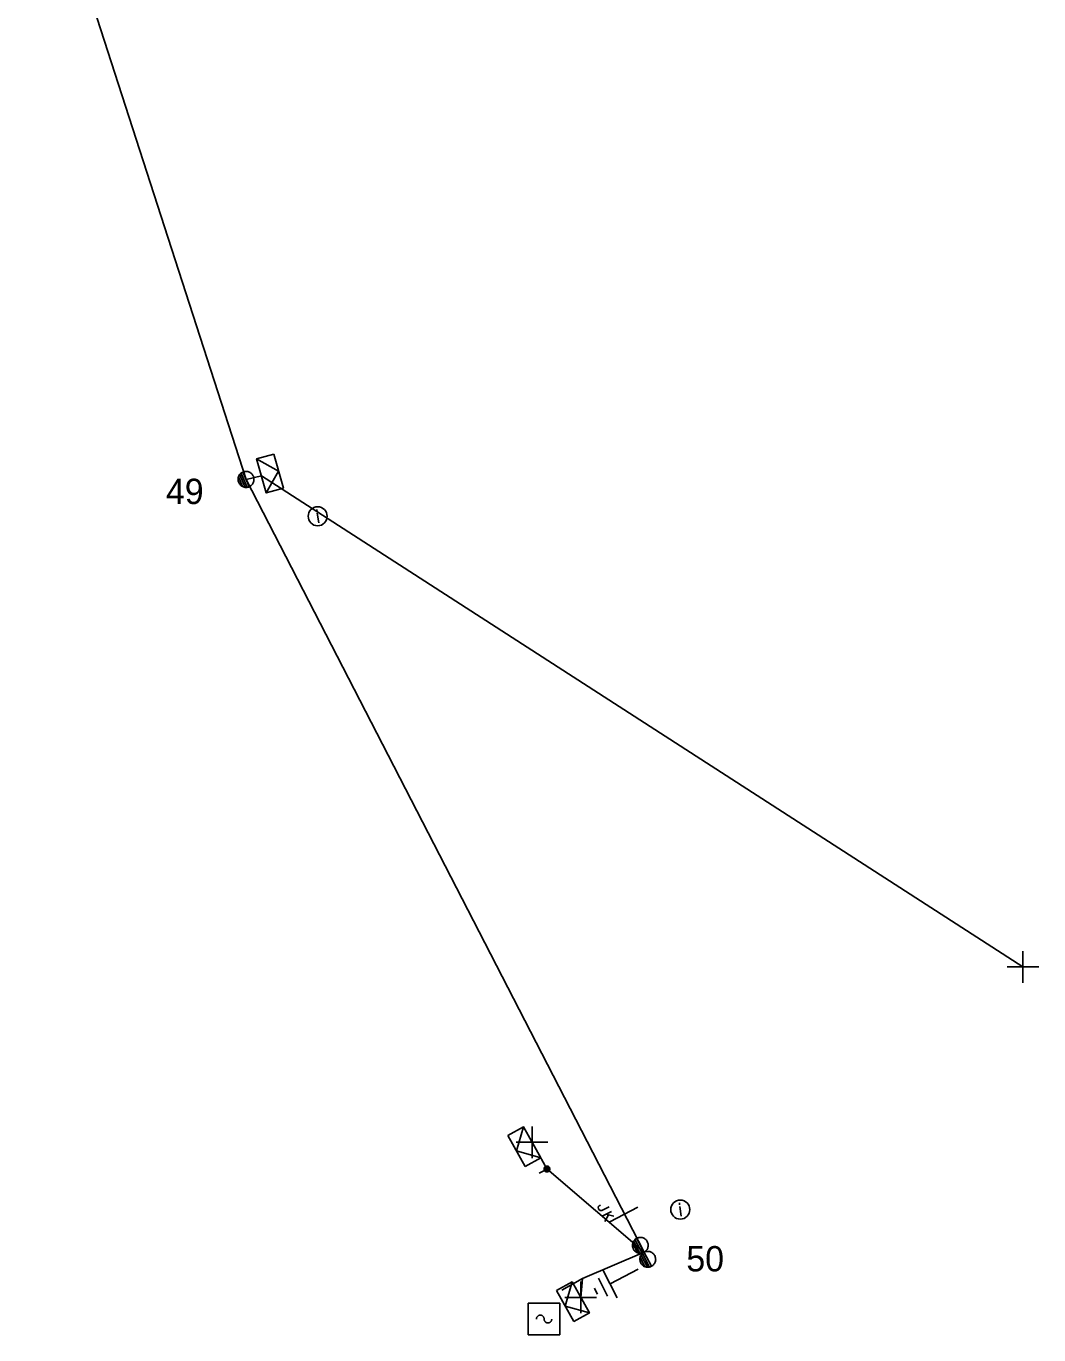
# Model space of a CAD drawing. Extents: x -544780 to -541582, y -1198995 to -1196551.
# Drawn here: x -544614.2 to -544574.2, y -1198551.5 to -1198499.8 of the extents above; entities that cross this region are included whole.
import ezdxf

# ---------------------------------------------------------------- set-up
doc = ezdxf.new("R2010")
doc.units = 0
for name, color, linetype in [('Vrstva 1', 7, 'Continuous'), ('Vrstva 10', 7, 'Continuous'), ('Vrstva 13', 7, 'Continuous'), ('Vrstva 14', 7, 'Continuous'), ('Vrstva 15', 7, 'Continuous'), ('Vrstva 18', 7, 'Continuous'), ('Vrstva 2', 7, 'Continuous'), ('Vrstva 31', 7, 'Continuous'), ('Vrstva 34', 7, 'Continuous'), ('Vrstva 36', 7, 'Continuous'), ('Vrstva 54', 7, 'Continuous'), ('Vrstva 59', 7, 'Continuous'), ('Vrstva 8', 7, 'Continuous'), ('Vrstva 9', 7, 'Continuous')]:
    doc.layers.add(name, color=color, linetype=linetype)

# ---------------------------------------------------------------- blocks, each defined once
blk = doc.blocks.new('NN440')
at = {"layer": 'Vrstva 2'}
for points in [[(0.63, 0), (0.63, 0.06), (0.62, 0.13), (0.6, 0.19), (0.58, 0.25), (0.55, 0.31), (0.51, 0.37), (0.47, 0.42), (0.42, 0.46), (0.37, 0.51), (0.32, 0.54), (0.26, 0.57), (0.2, 0.59), (0.13, 0.61), (0.07, 0.62), (0, 0.63), (-0.06, 0.62), (-0.13, 0.61), (-0.19, 0.59), (-0.26, 0.57), (-0.31, 0.54), (-0.37, 0.51), (-0.42, 0.46), (-0.47, 0.42), (-0.51, 0.37), (-0.54, 0.31), (-0.57, 0.25), (-0.6, 0.19), (-0.62, 0.13), (-0.63, 0.06), (-0.63, 0), (-0.63, -0.07), (-0.62, -0.14), (-0.6, -0.2), (-0.57, -0.26), (-0.54, -0.32), (-0.51, -0.37), (-0.47, -0.43), (-0.42, -0.47), (-0.37, -0.51), (-0.31, -0.55), (-0.26, -0.58), (-0.19, -0.6), (-0.13, -0.62), (-0.06, -0.63), (0, -0.63), (0.07, -0.63), (0.13, -0.62), (0.2, -0.6), (0.26, -0.58), (0.32, -0.55), (0.37, -0.51), (0.42, -0.47), (0.47, -0.43), (0.51, -0.37), (0.55, -0.32), (0.58, -0.26), (0.6, -0.2), (0.62, -0.14), (0.63, -0.07), (0.63, 0)], [(-0.63, 0), (0.63, 0)], [(-0.6, -0.18), (0.57, -0.18)], [(-0.51, -0.32), (0.5, -0.32)], [(-0.37, -0.47), (0.35, -0.47)]]:
    blk.add_lwpolyline(points, dxfattribs=at)
blk = doc.blocks.new('NN450')
at = {"layer": 'Vrstva 2'}
for points in [[(0, 0), (0, 0.07), (-0.01, 0.13), (-0.03, 0.19), (-0.05, 0.25), (-0.08, 0.31), (-0.12, 0.37), (-0.16, 0.42), (-0.21, 0.46), (-0.26, 0.51), (-0.31, 0.54), (-0.37, 0.57), (-0.43, 0.59), (-0.5, 0.61), (-0.56, 0.62), (-0.63, 0.62), (-0.69, 0.62), (-0.75, 0.61), (-0.82, 0.59), (-0.88, 0.57), (-0.94, 0.54), (-0.99, 0.51), (-1.04, 0.46), (-1.09, 0.42), (-1.13, 0.37), (-1.17, 0.31), (-1.2, 0.25), (-1.22, 0.19), (-1.24, 0.13), (-1.25, 0.07), (-1.25, 0), (-1.25, -0.07), (-1.24, -0.13), (-1.22, -0.19), (-1.2, -0.25), (-1.17, -0.31), (-1.13, -0.37), (-1.09, -0.42), (-1.04, -0.46), (-0.99, -0.51), (-0.94, -0.54), (-0.88, -0.57), (-0.82, -0.59), (-0.75, -0.61), (-0.69, -0.62), (-0.62, -0.63), (-0.56, -0.62), (-0.5, -0.61), (-0.43, -0.59), (-0.37, -0.57), (-0.31, -0.54), (-0.26, -0.51), (-0.21, -0.46), (-0.16, -0.42), (-0.12, -0.37), (-0.08, -0.31), (-0.05, -0.25), (-0.03, -0.19), (-0.01, -0.13), (0, -0.07), (0, 0)], [(1.25, 0), (1.25, 0.07), (1.24, 0.13), (1.22, 0.19), (1.2, 0.25), (1.17, 0.31), (1.13, 0.37), (1.09, 0.42), (1.04, 0.46), (0.99, 0.51), (0.94, 0.54), (0.88, 0.57), (0.82, 0.59), (0.75, 0.61), (0.69, 0.62), (0.62, 0.62), (0.56, 0.62), (0.5, 0.61), (0.43, 0.59), (0.37, 0.57), (0.31, 0.54), (0.26, 0.51), (0.21, 0.46), (0.16, 0.42), (0.12, 0.37), (0.08, 0.31), (0.05, 0.25), (0.03, 0.19), (0.01, 0.13), (0, 0.07), (0, 0), (0, -0.07), (0.01, -0.13), (0.03, -0.19), (0.05, -0.25), (0.08, -0.31), (0.12, -0.37), (0.16, -0.42), (0.21, -0.46), (0.26, -0.51), (0.31, -0.54), (0.37, -0.57), (0.43, -0.59), (0.5, -0.61), (0.56, -0.62), (0.63, -0.63), (0.69, -0.62), (0.75, -0.61), (0.82, -0.59), (0.88, -0.57), (0.94, -0.54), (0.99, -0.51), (1.04, -0.46), (1.09, -0.42), (1.13, -0.37), (1.17, -0.31), (1.2, -0.25), (1.22, -0.19), (1.24, -0.13), (1.25, -0.07), (1.25, 0)], [(-1.25, 0), (1.25, 0)], [(-1.23, -0.16), (-0.02, -0.16)], [(-1.16, -0.32), (-0.09, -0.32)], [(-1.03, -0.47), (-0.22, -0.47)], [(0.02, -0.16), (1.23, -0.16)], [(0.09, -0.32), (1.16, -0.32)], [(0.22, -0.47), (1.03, -0.47)]]:
    blk.add_lwpolyline(points, dxfattribs=at)
blk = doc.blocks.new('NN840')
at = {"layer": 'Vrstva 15'}
for points in [[(0.003, 0.619), (0.003, -0.631)], [(-0.538, -0.385), (-0.538, -0.71)], [(-0.332, -0.385), (-0.332, -0.798)], [(-0.332, -0.641), (-0.125, -0.385)], [(-0.745, -0.71), (-0.745, -0.66)], [(-0.73, -0.764), (-0.745, -0.71)], [(-0.657, -0.798), (-0.73, -0.764)], [(-0.627, -0.798), (-0.657, -0.798)], [(-0.558, -0.764), (-0.627, -0.798)], [(-0.538, -0.71), (-0.558, -0.764)], [(-0.263, -0.557), (-0.091, -0.798)]]:
    blk.add_lwpolyline(points, dxfattribs=at)
blk = doc.blocks.new('NN770')
at = {"layer": 'Vrstva 10'}
for p, q in [((0.002, 0.187), (0.002, 0.263)), ((0.002, -0.276), (0.002, 0.111))]:
    blk.add_line(p, q, dxfattribs=at)
blk.add_circle((0, -0.008), 0.375, dxfattribs=at)
blk = doc.blocks.new('NN800')
at = {"layer": 'Vrstva 1'}
for points in [[(-0.442, 0.442), (0.442, -0.442)], [(-0.442, -0.442), (0.442, 0.442)]]:
    blk.add_lwpolyline(points, dxfattribs=at)
blk = doc.blocks.new('NN630')
at = {"layer": 'Vrstva 9'}
for points in [[(-0.003, -0.7), (-0.703, 0)], [(-0.703, -0.7), (-0.703, 0), (0.697, 0), (0.697, -0.7)], [(-0.003, -0.7), (0.697, 0)], [(-0.703, -0.7), (0.697, -0.7)]]:
    blk.add_lwpolyline(points, dxfattribs=at)
blk = doc.blocks.new('NN810')
at = {"layer": 'Vrstva 14'}
for points in [[(0.004, -0.64), (0.004, -1.89)], [(0.629, -1.89), (-0.621, -1.89)], [(0.388, -2.2), (-0.399, -2.2)], [(0.004, -2.515), (-0.124, -2.515)], [(0.137, -2.515), (0.004, -2.515)]]:
    blk.add_lwpolyline(points, dxfattribs=at)
blk = doc.blocks.new('NN740')
at = {"layer": 'Vrstva 1'}
for points in [[(0.624, 0.624), (-0.626, 0.624)], [(-0.626, 0.624), (-0.626, -0.626)], [(0.624, -0.626), (0.624, 0.624)], [(-0.001, -0.001), (-0.002, 0.015), (-0.004, 0.031), (-0.008, 0.046), (-0.014, 0.061), (-0.021, 0.075), (-0.03, 0.089), (-0.04, 0.101), (-0.051, 0.112), (-0.063, 0.123), (-0.077, 0.131), (-0.091, 0.139), (-0.106, 0.145), (-0.121, 0.149), (-0.137, 0.151), (-0.153, 0.152), (-0.169, 0.151), (-0.185, 0.149), (-0.2, 0.145), (-0.215, 0.139), (-0.229, 0.132), (-0.243, 0.123), (-0.255, 0.113), (-0.266, 0.102), (-0.276, 0.09), (-0.285, 0.076), (-0.293, 0.062), (-0.298, 0.047), (-0.303, 0.032), (-0.305, 0.016), (-0.306, 0), (-0.306, -0.001)], [(-0.001, -0.001), (0, -0.017), (0.002, -0.032), (0.006, -0.048), (0.011, -0.062), (0.018, -0.077), (0.026, -0.09), (0.036, -0.102), (0.047, -0.114), (0.059, -0.124), (0.072, -0.133), (0.085, -0.14), (0.1, -0.146), (0.115, -0.15), (0.131, -0.153), (0.146, -0.154), (0.162, -0.154), (0.178, -0.151), (0.193, -0.148), (0.208, -0.142), (0.222, -0.135), (0.235, -0.127), (0.247, -0.118), (0.259, -0.107), (0.269, -0.095), (0.278, -0.082), (0.285, -0.068), (0.291, -0.053), (0.295, -0.038), (0.298, -0.023), (0.299, -0.007), (0.299, -0.006)], [(-0.626, -0.626), (0.624, -0.626)]]:
    blk.add_lwpolyline(points, dxfattribs=at)
blk = doc.blocks.new('NN500')
at = {"layer": 'Vrstva 2'}
for points in [[(0, -0.24), (0.02, -0.23), (0.05, -0.23), (0.07, -0.22), (0.09, -0.22), (0.12, -0.2), (0.14, -0.19), (0.16, -0.18), (0.17, -0.16), (0.19, -0.14), (0.2, -0.12), (0.21, -0.1), (0.22, -0.07), (0.23, -0.05), (0.23, -0.02), (0.23, 0), (0.23, 0.02), (0.23, 0.05), (0.22, 0.07), (0.21, 0.1), (0.2, 0.12), (0.19, 0.14), (0.17, 0.16), (0.16, 0.17), (0.14, 0.19), (0.12, 0.2), (0.09, 0.21), (0.07, 0.22), (0.05, 0.23), (0.02, 0.23), (0, 0.23), (-0.03, 0.23), (-0.05, 0.23), (-0.07, 0.22), (-0.1, 0.21), (-0.12, 0.2), (-0.14, 0.19), (-0.16, 0.17), (-0.18, 0.16), (-0.19, 0.14), (-0.2, 0.12), (-0.22, 0.1), (-0.22, 0.07), (-0.23, 0.05), (-0.23, 0.02), (-0.24, 0), (-0.23, -0.02), (-0.23, -0.05), (-0.22, -0.07), (-0.22, -0.1), (-0.2, -0.12), (-0.19, -0.14), (-0.18, -0.16), (-0.16, -0.18), (-0.14, -0.19), (-0.12, -0.2), (-0.1, -0.22), (-0.07, -0.22), (-0.05, -0.23), (-0.03, -0.23), (0, -0.24)], [(0, -0.24), (0.02, -0.23), (0.05, -0.23), (0.07, -0.22), (0.09, -0.22), (0.12, -0.2), (0.14, -0.19), (0.16, -0.18), (0.17, -0.16), (0.19, -0.14), (0.2, -0.12), (0.21, -0.1), (0.22, -0.07), (0.23, -0.05), (0.23, -0.02), (0.23, 0), (0.23, 0.02), (0.23, 0.05), (0.22, 0.07), (0.21, 0.1), (0.2, 0.12), (0.19, 0.14), (0.17, 0.16), (0.16, 0.17), (0.14, 0.19), (0.12, 0.2), (0.09, 0.21), (0.07, 0.22), (0.05, 0.23), (0.02, 0.23), (0, 0.23), (-0.03, 0.23), (-0.05, 0.23), (-0.07, 0.22), (-0.1, 0.21), (-0.12, 0.2), (-0.14, 0.19), (-0.16, 0.17), (-0.18, 0.16), (-0.19, 0.14), (-0.2, 0.12), (-0.22, 0.1), (-0.22, 0.07), (-0.23, 0.05), (-0.23, 0.02), (-0.24, 0), (-0.23, -0.02), (-0.23, -0.05), (-0.22, -0.07), (-0.22, -0.1), (-0.2, -0.12), (-0.19, -0.14), (-0.18, -0.16), (-0.16, -0.18), (-0.14, -0.19), (-0.12, -0.2), (-0.1, -0.22), (-0.07, -0.22), (-0.05, -0.23), (-0.03, -0.23), (0, -0.24)], [(0, -0.21), (0.02, -0.2), (0.04, -0.2), (0.06, -0.2), (0.08, -0.19), (0.1, -0.18), (0.12, -0.17), (0.14, -0.15), (0.15, -0.14), (0.16, -0.12), (0.18, -0.1), (0.19, -0.08), (0.19, -0.06), (0.2, -0.04), (0.2, -0.02), (0.2, 0), (0.2, 0.02), (0.2, 0.04), (0.19, 0.06), (0.19, 0.08), (0.18, 0.1), (0.16, 0.12), (0.15, 0.14), (0.14, 0.15), (0.12, 0.17), (0.1, 0.18), (0.08, 0.19), (0.06, 0.19), (0.04, 0.2), (0.02, 0.2), (0, 0.2), (-0.02, 0.2), (-0.04, 0.2), (-0.06, 0.19), (-0.08, 0.19), (-0.1, 0.18), (-0.12, 0.17), (-0.14, 0.15), (-0.15, 0.14), (-0.17, 0.12), (-0.18, 0.1), (-0.19, 0.08), (-0.2, 0.06), (-0.2, 0.04), (-0.21, 0.02), (-0.21, 0), (-0.21, -0.02), (-0.2, -0.04), (-0.2, -0.06), (-0.19, -0.08), (-0.18, -0.1), (-0.17, -0.12), (-0.15, -0.14), (-0.14, -0.15), (-0.12, -0.17), (-0.1, -0.18), (-0.08, -0.19), (-0.06, -0.2), (-0.04, -0.2), (-0.02, -0.2), (0, -0.21)], [(0, -0.18), (0.02, -0.18), (0.04, -0.17), (0.05, -0.17), (0.07, -0.16), (0.09, -0.15), (0.1, -0.14), (0.12, -0.13), (0.13, -0.12), (0.14, -0.1), (0.15, -0.09), (0.16, -0.07), (0.17, -0.05), (0.17, -0.04), (0.17, -0.02), (0.17, 0), (0.17, 0.02), (0.17, 0.04), (0.17, 0.05), (0.16, 0.07), (0.15, 0.09), (0.14, 0.1), (0.13, 0.12), (0.12, 0.13), (0.1, 0.14), (0.09, 0.15), (0.07, 0.16), (0.05, 0.17), (0.04, 0.17), (0.02, 0.17), (0, 0.18), (-0.02, 0.17), (-0.04, 0.17), (-0.06, 0.17), (-0.07, 0.16), (-0.09, 0.15), (-0.1, 0.14), (-0.12, 0.13), (-0.13, 0.12), (-0.14, 0.1), (-0.15, 0.09), (-0.16, 0.07), (-0.17, 0.05), (-0.17, 0.04), (-0.18, 0.02), (-0.18, 0), (-0.18, -0.02), (-0.17, -0.04), (-0.17, -0.05), (-0.16, -0.07), (-0.15, -0.09), (-0.14, -0.1), (-0.13, -0.12), (-0.12, -0.13), (-0.1, -0.14), (-0.09, -0.15), (-0.07, -0.16), (-0.06, -0.17), (-0.04, -0.17), (-0.02, -0.18), (0, -0.18)], [(0, -0.15), (0.01, -0.15), (0.03, -0.14), (0.04, -0.14), (0.06, -0.13), (0.07, -0.13), (0.08, -0.12), (0.1, -0.11), (0.11, -0.1), (0.12, -0.09), (0.13, -0.07), (0.13, -0.06), (0.14, -0.05), (0.14, -0.03), (0.14, -0.02), (0.14, 0), (0.14, 0.01), (0.14, 0.03), (0.14, 0.04), (0.13, 0.06), (0.13, 0.07), (0.12, 0.09), (0.11, 0.1), (0.1, 0.11), (0.08, 0.12), (0.07, 0.13), (0.06, 0.13), (0.04, 0.14), (0.03, 0.14), (0.01, 0.14), (0, 0.15), (-0.02, 0.14), (-0.03, 0.14), (-0.05, 0.14), (-0.06, 0.13), (-0.07, 0.13), (-0.09, 0.12), (-0.1, 0.11), (-0.11, 0.1), (-0.12, 0.09), (-0.13, 0.07), (-0.13, 0.06), (-0.14, 0.04), (-0.14, 0.03), (-0.15, 0.01), (-0.15, 0), (-0.15, -0.02), (-0.14, -0.03), (-0.14, -0.05), (-0.13, -0.06), (-0.13, -0.07), (-0.12, -0.09), (-0.11, -0.1), (-0.1, -0.11), (-0.09, -0.12), (-0.07, -0.13), (-0.06, -0.13), (-0.05, -0.14), (-0.03, -0.14), (-0.02, -0.15), (0, -0.15)], [(0, -0.12), (0.01, -0.12), (0.02, -0.11), (0.03, -0.11), (0.05, -0.11), (0.06, -0.1), (0.07, -0.09), (0.08, -0.09), (0.09, -0.08), (0.09, -0.07), (0.1, -0.06), (0.11, -0.05), (0.11, -0.04), (0.11, -0.02), (0.11, -0.01), (0.12, 0), (0.11, 0.01), (0.11, 0.02), (0.11, 0.04), (0.11, 0.05), (0.1, 0.06), (0.09, 0.07), (0.09, 0.08), (0.08, 0.09), (0.07, 0.09), (0.06, 0.1), (0.05, 0.11), (0.03, 0.11), (0.02, 0.11), (0.01, 0.12), (0, 0.12), (-0.01, 0.12), (-0.03, 0.11), (-0.04, 0.11), (-0.05, 0.11), (-0.06, 0.1), (-0.07, 0.09), (-0.08, 0.09), (-0.09, 0.08), (-0.1, 0.07), (-0.1, 0.06), (-0.11, 0.05), (-0.11, 0.04), (-0.12, 0.02), (-0.12, 0.01), (-0.12, 0), (-0.12, -0.01), (-0.12, -0.02), (-0.11, -0.04), (-0.11, -0.05), (-0.1, -0.06), (-0.1, -0.07), (-0.09, -0.08), (-0.08, -0.09), (-0.07, -0.09), (-0.06, -0.1), (-0.05, -0.11), (-0.04, -0.11), (-0.03, -0.11), (-0.01, -0.12), (0, -0.12)], [(0, -0.09), (0.01, -0.09), (0.02, -0.09), (0.03, -0.08), (0.03, -0.08), (0.04, -0.08), (0.05, -0.07), (0.06, -0.07), (0.06, -0.06), (0.07, -0.05), (0.07, -0.04), (0.08, -0.04), (0.08, -0.03), (0.08, -0.02), (0.09, -0.01), (0.09, 0), (0.09, 0.01), (0.08, 0.02), (0.08, 0.03), (0.08, 0.03), (0.07, 0.04), (0.07, 0.05), (0.06, 0.06), (0.06, 0.06), (0.05, 0.07), (0.04, 0.07), (0.03, 0.08), (0.03, 0.08), (0.02, 0.08), (0.01, 0.09), (0, 0.09), (-0.01, 0.09), (-0.02, 0.08), (-0.03, 0.08), (-0.04, 0.08), (-0.04, 0.07), (-0.05, 0.07), (-0.06, 0.06), (-0.07, 0.06), (-0.07, 0.05), (-0.08, 0.04), (-0.08, 0.03), (-0.08, 0.03), (-0.09, 0.02), (-0.09, 0.01), (-0.09, 0), (-0.09, -0.01), (-0.09, -0.02), (-0.08, -0.03), (-0.08, -0.04), (-0.08, -0.04), (-0.07, -0.05), (-0.07, -0.06), (-0.06, -0.07), (-0.05, -0.07), (-0.04, -0.08), (-0.04, -0.08), (-0.03, -0.08), (-0.02, -0.09), (-0.01, -0.09), (0, -0.09)], [(0, -0.06), (0, -0.06), (0.01, -0.06), (0.02, -0.05), (0.02, -0.05), (0.03, -0.05), (0.03, -0.05), (0.04, -0.04), (0.04, -0.04), (0.05, -0.03), (0.05, -0.03), (0.05, -0.02), (0.05, -0.02), (0.05, -0.01), (0.06, -0.01), (0.06, 0), (0.06, 0.01), (0.05, 0.01), (0.05, 0.02), (0.05, 0.02), (0.05, 0.03), (0.05, 0.03), (0.04, 0.04), (0.04, 0.04), (0.03, 0.05), (0.03, 0.05), (0.02, 0.05), (0.02, 0.05), (0.01, 0.06), (0, 0.06), (0, 0.06), (-0.01, 0.06), (-0.01, 0.06), (-0.02, 0.05), (-0.02, 0.05), (-0.03, 0.05), (-0.03, 0.05), (-0.04, 0.04), (-0.04, 0.04), (-0.05, 0.03), (-0.05, 0.03), (-0.05, 0.02), (-0.06, 0.02), (-0.06, 0.01), (-0.06, 0.01), (-0.06, 0), (-0.06, -0.01), (-0.06, -0.01), (-0.06, -0.02), (-0.05, -0.02), (-0.05, -0.03), (-0.05, -0.03), (-0.04, -0.04), (-0.04, -0.04), (-0.03, -0.05), (-0.03, -0.05), (-0.02, -0.05), (-0.02, -0.05), (-0.01, -0.06), (-0.01, -0.06), (0, -0.06)], [(0, -0.03), (0, -0.03), (0, -0.03), (0.01, -0.03), (0.01, -0.03), (0.01, -0.02), (0.02, -0.02), (0.02, -0.02), (0.02, -0.02), (0.02, -0.02), (0.02, -0.01), (0.02, -0.01), (0.03, -0.01), (0.03, -0.01), (0.03, 0), (0.03, 0), (0.03, 0), (0.03, 0.01), (0.03, 0.01), (0.02, 0.01), (0.02, 0.01), (0.02, 0.02), (0.02, 0.02), (0.02, 0.02), (0.02, 0.02), (0.01, 0.02), (0.01, 0.02), (0.01, 0.03), (0, 0.03), (0, 0.03), (0, 0.03), (0, 0.03), (-0.01, 0.03), (-0.01, 0.03), (-0.01, 0.02), (-0.02, 0.02), (-0.02, 0.02), (-0.02, 0.02), (-0.02, 0.02), (-0.02, 0.02), (-0.03, 0.01), (-0.03, 0.01), (-0.03, 0.01), (-0.03, 0.01), (-0.03, 0), (-0.03, 0), (-0.03, 0), (-0.03, -0.01), (-0.03, -0.01), (-0.03, -0.01), (-0.03, -0.01), (-0.02, -0.02), (-0.02, -0.02), (-0.02, -0.02), (-0.02, -0.02), (-0.02, -0.02), (-0.01, -0.03), (-0.01, -0.03), (-0.01, -0.03), (0, -0.03), (0, -0.03)], [(0.23, 0), (0.7, 0)]]:
    blk.add_lwpolyline(points, dxfattribs=at)
blk = doc.blocks.new('NN510')
at = {"layer": 'Vrstva 2'}
blk.add_lwpolyline([(0.001, 0.002), (0.001, 0.939)], dxfattribs=at)

msp = doc.modelspace()

# ---------------------------------------------------------------- linework, layer by layer
at = {"layer": 'Vrstva 1'}
msp.add_lwpolyline([(-544606.56, -1198459.4), (-544614.155, -1198490.827), (-544605.475, -1198517.706), (-544589.764, -1198548.223)], dxfattribs=at)
at = {"layer": 'Vrstva 54'}
msp.add_lwpolyline([(-544589.764, -1198548.223), (-544592.188, -1198549.261), (-544592.261, -1198550.006)], dxfattribs=at)
at = {"layer": 'Vrstva 59'}
msp.add_lwpolyline([(-544605.475, -1198517.706), (-544604.867, -1198517.568), (-544574.805, -1198536.955)], dxfattribs=at)
at = {"layer": 'Vrstva 8'}
msp.add_lwpolyline([(-544589.764, -1198548.223), (-544593.596, -1198544.933), (-544594.182, -1198543.879)], dxfattribs=at)

# ---------------------------------------------------------------- block references
at = {"layer": 'Vrstva 13'}
for name, p, xscale, yscale, rotation in [('NN440', (-544605.475, -1198517.706), 0.5000000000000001, 0.4999999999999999, -67.12448892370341), ('NN500', (-544593.596, -1198544.933), 0.5, 0.49999999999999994, -150.85799991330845), ('NN450', (-544589.764, -1198548.223), 0.49999999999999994, 0.5, -62.037694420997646)]:
    msp.add_blockref(name, p, dxfattribs=dict(at, xscale=xscale, yscale=yscale, rotation=rotation))
at = {"layer": 'Vrstva 13', "rotation": 119.19531114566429}
msp.add_blockref('NN510', (-544592.188, -1198549.261), dxfattribs=at)
at = {"layer": 'Vrstva 15', "rotation": -62.759330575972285}
msp.add_blockref('NN810', (-544589.428, -1198548.596), dxfattribs=at)
at = {"layer": 'Vrstva 18', "rotation": -62.759330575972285}
msp.add_blockref('NN840', (-544590.557, -1198546.725), dxfattribs=at)
at = {"layer": 'Vrstva 31'}
for p, rotation in [((-544604.867, -1198517.568), 105.78679207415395), ((-544594.182, -1198543.88), -60.8578527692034), ((-544592.261, -1198550.006), -60.804688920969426)]:
    msp.add_blockref('NN630', p, dxfattribs=dict(at, rotation=rotation))
at = {"layer": 'Vrstva 34'}
for p, rotation in [((-544574.805, -1198536.955), 45), ((-544594.182, -1198543.879), 45.00000009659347), ((-544592.261, -1198550.006), 45)]:
    msp.add_blockref('NN800', p, dxfattribs=dict(at, rotation=rotation))
msp.add_blockref('NN740', (-544593.707, -1198550.855), dxfattribs=at)
at = {"layer": 'Vrstva 36'}
for p, rotation in [((-544602.649, -1198519.155), 8.03866094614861), ((-544588.334, -1198546.529), 8.038661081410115)]:
    msp.add_blockref('NN770', p, dxfattribs=dict(at, rotation=rotation))

# ---------------------------------------------------------------- texts
at = {"layer": 'Vrstva 14'}
for s, p in [('49', (-544608.637, -1198518.681)), ('50', (-544588.095, -1198548.977))]:
    msp.add_text(s, height=1, dxfattribs=at).set_placement(p)

doc.saveas('drawing.dxf')
